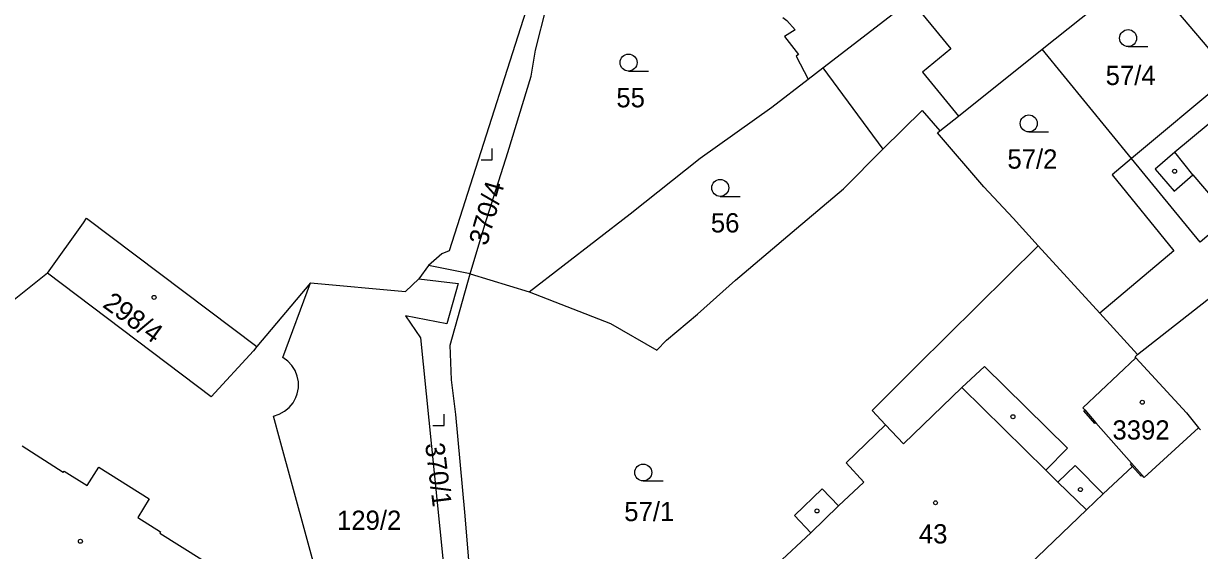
# Model space of a CAD drawing. Extents: x -679220 to -673243, y -1075091 to -1066557.
# Drawn here: x -676665 to -676560.9, y -1071449.2 to -1071402.6 of the extents above; entities that cross this region are included whole.
import ezdxf

# ---------------------------------------------------------------- set-up
doc = ezdxf.new("R2010")
doc.units = 0
for name, color, linetype in [('Hranice parcel', 7, 'Continuous'), ('Parcelní čísla', 7, 'Continuous'), ('Vnitřní kresba', 7, 'Continuous'), ('Značky budov', 7, 'Continuous'), ('Značky kultur', 7, 'Continuous')]:
    doc.layers.add(name, color=color, linetype=linetype)

msp = doc.modelspace()

# ---------------------------------------------------------------- linework, layer by layer
at = {"layer": 'Hranice parcel'}
for p, q in [((-676574.86, -1071404.84), (-676566.05, -1071397.82)), ((-676566.05, -1071397.82), (-676558.15, -1071407.15)), ((-676566.95, -1071414.5), (-676574.86, -1071404.84)), ((-676595.55, -1071407.49), (-676594.27, -1071406.5)), ((-676594.27, -1071406.5), (-676588.94, -1071413.68)), ((-676558.15, -1071407.15), (-676566.95, -1071414.5)), ((-676569.76, -1071428.19), (-676575.21, -1071422.22)), ((-676629.15, -1071423.95), (-676629.99, -1071425.14)), ((-676625.45, -1071424.7), (-676629.15, -1071423.95)), ((-676662.84, -1071424.65), (-676670.63, -1071430.85)), ((-676625.45, -1071424.7), (-676620.24, -1071426.29)), ((-676639.58, -1071425.49), (-676644.31, -1071431.12)), ((-676642.01, -1071432.1), (-676639.58, -1071425.49)), ((-676566.43, -1071431.83), (-676569.76, -1071428.19)), ((-676560.86, -1071438.5), (-676561.02, -1071438.3))]:
    msp.add_line(p, q, dxfattribs=at)
for points in [[(-676617.88, -1071388.31), (-676618.61, -1071388.69), (-676619.11, -1071389.11), (-676619.75, -1071389.94), (-676620.01, -1071390.56), (-676620.07, -1071392.77), (-676619.59, -1071394.13), (-676619.18, -1071394.93), (-676618.66, -1071395.65), (-676627.3, -1071422.68), (-676627.95, -1071422.94), (-676629.15, -1071423.95)], [(-676625.45, -1071424.7), (-676624.15, -1071420.38), (-676622.13, -1071413.98), (-676620.04, -1071407.23), (-676619.66, -1071404.92), (-676618.7, -1071401.1), (-676617.84, -1071396.43), (-676618.04, -1071394.99), (-676619.3, -1071392.29), (-676618.86, -1071390.8), (-676617.78, -1071390.15), (-676616.76, -1071389.74), (-676615.7, -1071390.33), (-676615.42, -1071389.7)], [(-676594.27, -1071406.5), (-676586.46, -1071400.51), (-676585.72, -1071399.94), (-676583.23, -1071398.03), (-676572.66, -1071389.87)], [(-676597.79, -1071402.04), (-676597.44, -1071402.3), (-676596.7, -1071403.12), (-676597.65, -1071403.73), (-676596.42, -1071405.3), (-676596.62, -1071405.46), (-676595.55, -1071407.49)], [(-676583.91, -1071412.06), (-676582.27, -1071410.75), (-676574.86, -1071404.84)], [(-676620.24, -1071426.29), (-676611.29, -1071419.39), (-676605.1, -1071414.47), (-676598.76, -1071409.97), (-676595.55, -1071407.49)], [(-676588.94, -1071413.68), (-676587.18, -1071411.93), (-676585.48, -1071410.26), (-676583.91, -1071412.06)], [(-676575.21, -1071422.22), (-676577.43, -1071419.78), (-676580.01, -1071417), (-676584.11, -1071412.24), (-676583.91, -1071412.06)], [(-676620.24, -1071426.29), (-676613.03, -1071429.08), (-676608.93, -1071431.46), (-676608.08, -1071430.55), (-676605.33, -1071428.25), (-676601.97, -1071425.26), (-676596.59, -1071420.68), (-676592.44, -1071417.18), (-676588.94, -1071413.68)], [(-676566.95, -1071414.5), (-676568.67, -1071415.94), (-676563.2, -1071422.66), (-676569.76, -1071428.19)], [(-676550.13, -1071416.68), (-676556.21, -1071421.85), (-676556.38, -1071422.01), (-676558.31, -1071419.73), (-676560.88, -1071421.91), (-676566.95, -1071414.5)], [(-676662.84, -1071424.65), (-676659.66, -1071420.19), (-676659.39, -1071419.78), (-676644.31, -1071431.12)], [(-676575.21, -1071422.22), (-676585.95, -1071432.82), (-676589.88, -1071436.78), (-676588.71, -1071438.04), (-676592.2, -1071441.42), (-676590.62, -1071443.1), (-676592.88, -1071445.22), (-676594.32, -1071443.69), (-676596.77, -1071446.05), (-676595.33, -1071447.58), (-676598.3, -1071450.36), (-676587.79, -1071461.53)], [(-676566.43, -1071431.83), (-676555.25, -1071423.07), (-676554.99, -1071422.87), (-676554.89, -1071423.01), (-676554.71, -1071422.88), (-676554.42, -1071423.27), (-676549.68, -1071428.95)], [(-676644.31, -1071431.12), (-676644.61, -1071431.52), (-676648.35, -1071435.57), (-676662.84, -1071424.65)], [(-676639.58, -1071425.49), (-676631.17, -1071426.26), (-676629.99, -1071425.14)], [(-676629.99, -1071425.14), (-676626.5, -1071425.54), (-676627.51, -1071429.11), (-676631.18, -1071428.42), (-676629.85, -1071430.36), (-676627.63, -1071452.18), (-676627.06, -1071457.4), (-676627.95, -1071458.12), (-676628.5, -1071459.17), (-676628.73, -1071459.98)], [(-676624.32, -1071460.51), (-676624.77, -1071456.53), (-676625.37, -1071452.45), (-676625.93, -1071445.76), (-676626.71, -1071437.13), (-676627.11, -1071434.06), (-676627.22, -1071431), (-676625.45, -1071424.7)], [(-676642.84, -1071437.27), (-676642.34, -1071437.11), (-676641.87, -1071436.85), (-676641.46, -1071436.52), (-676641.12, -1071436.11), (-676640.86, -1071435.64), (-676640.74, -1071435.31), (-676640.64, -1071434.79), (-676640.64, -1071434.26), (-676640.74, -1071433.74), (-676640.94, -1071433.25), (-676641.22, -1071432.8), (-676641.58, -1071432.41), (-676642.01, -1071432.1)], [(-676566.87, -1071441.72), (-676567.04, -1071441.52), (-676566.95, -1071441.44), (-676570.1, -1071437.86), (-676570.19, -1071437.94), (-676571.18, -1071436.81), (-676571.09, -1071436.73), (-676571.25, -1071436.55), (-676566.56, -1071432.12)], [(-676566.56, -1071432.12), (-676566.64, -1071432.03), (-676566.43, -1071431.83)], [(-676566.56, -1071432.12), (-676562.09, -1071436.98), (-676561.02, -1071438.3)], [(-676636.38, -1071460.95), (-676636.42, -1071460.8), (-676642.28, -1071439.33), (-676642.84, -1071437.27)], [(-676561.02, -1071438.3), (-676565.83, -1071442.71), (-676566, -1071442.51), (-676566.1, -1071442.59), (-676566.87, -1071441.72)], [(-676557.42, -1071466.86), (-676557.95, -1071466.4), (-676558.07, -1071466.32), (-676558.3, -1071466.23), (-676558.56, -1071466.19), (-676558.82, -1071466.22), (-676559.09, -1071466.31), (-676559.32, -1071466.47), (-676559.94, -1071467.01), (-676560.51, -1071466.49), (-676560.28, -1071466.24), (-676576.7, -1071451.11), (-676570.92, -1071445.57), (-676569.45, -1071444.14), (-676566.87, -1071441.72)]]:
    msp.add_lwpolyline(points, dxfattribs=at)
at = {"layer": 'Vnitřní kresba'}
for p, q in [((-676586.46, -1071400.51), (-676582.93, -1071404.81)), ((-676582.93, -1071404.81), (-676585.44, -1071406.87)), ((-676585.44, -1071406.87), (-676582.27, -1071410.75)), ((-676556.84, -1071408.71), (-676563.12, -1071413.94)), ((-676563.12, -1071413.94), (-676564.85, -1071415.45)), ((-676561.53, -1071415.94), (-676563.12, -1071413.94)), ((-676564.85, -1071415.45), (-676563.18, -1071417.38)), ((-676563.18, -1071417.38), (-676561.53, -1071415.94)), ((-676561.53, -1071415.94), (-676558.31, -1071419.73)), ((-676581.95, -1071434.76), (-676579.96, -1071432.88)), ((-676579.96, -1071432.88), (-676572.62, -1071440.12)), ((-676587.13, -1071439.72), (-676581.95, -1071434.76)), ((-676581.95, -1071434.76), (-676574.53, -1071442.05)), ((-676571.09, -1071436.73), (-676570.1, -1071437.86)), ((-676588.71, -1071438.04), (-676587.13, -1071439.72)), ((-676661.44, -1071442.27), (-676665.07, -1071439.94)), ((-676574.53, -1071442.05), (-676572.62, -1071440.12)), ((-676659.34, -1071443.41), (-676658.31, -1071441.78)), ((-676658.31, -1071441.78), (-676653.84, -1071444.6)), ((-676573.46, -1071443.1), (-676571.95, -1071441.65)), ((-676569.45, -1071444.14), (-676571.95, -1071441.65)), ((-676566.95, -1071441.44), (-676566, -1071442.51)), ((-676661.44, -1071442.27), (-676661.35, -1071442.14)), ((-676661.35, -1071442.14), (-676659.34, -1071443.41)), ((-676574.53, -1071442.05), (-676573.46, -1071443.1)), ((-676573.46, -1071443.1), (-676570.92, -1071445.57)), ((-676653.84, -1071444.6), (-676654.84, -1071446.24)), ((-676595.33, -1071447.58), (-676592.88, -1071445.22)), ((-676654.84, -1071446.24), (-676652.83, -1071447.51)), ((-676652.83, -1071447.51), (-676652.91, -1071447.63)), ((-676652.91, -1071447.63), (-676649.19, -1071449.94))]:
    msp.add_line(p, q, dxfattribs=at)
at = {"layer": 'Značky budov'}
for centre in [(-676563.14, -1071415.63), (-676653.41, -1071426.78), (-676566, -1071436.05), (-676577.44, -1071437.33), (-676571.47, -1071443.77), (-676584.29, -1071444.94), (-676594.77, -1071445.66), (-676659.93, -1071448.34)]:
    msp.add_circle(centre, 0.175, dxfattribs=at)
at = {"layer": 'Značky kultur'}
for p, q in [((-676567.25, -1071404.61), (-676565.5, -1071404.61)), ((-676611.44, -1071406.78), (-676609.69, -1071406.78)), ((-676576.04, -1071412.15), (-676574.29, -1071412.15)), ((-676623.49, -1071414.63), (-676623.49, -1071413.63)), ((-676624.49, -1071414.63), (-676623.49, -1071414.63)), ((-676603.33, -1071417.85), (-676601.58, -1071417.85)), ((-676627.76, -1071438.11), (-676627.76, -1071437.11)), ((-676628.76, -1071438.11), (-676627.76, -1071438.11)), ((-676610.14, -1071443.01), (-676608.39, -1071443.01))]:
    msp.add_line(p, q, dxfattribs=at)
for centre in [(-676567.25, -1071403.86), (-676611.44, -1071406.03), (-676576.04, -1071411.4), (-676603.33, -1071417.1), (-676610.14, -1071442.26)]:
    msp.add_circle(centre, 0.75, dxfattribs=at)

# ---------------------------------------------------------------- texts
at = {"layer": 'Parcelní čísla'}
for s, p in [('57/4', (-676569.24, -1071408.01)), ('55', (-676612.52, -1071409.98)), ('57/2', (-676577.93, -1071415.4)), ('56', (-676604.16, -1071421.04)), ('3392', (-676568.64, -1071439.35)), ('57/1', (-676611.82, -1071446.56)), ('129/2', (-676637.23, -1071447.33)), ('43', (-676585.76, -1071448.53))]:
    msp.add_text(s, height=1.7, dxfattribs=at).set_placement(p)
for s, rotation, p in [('370/4', 74, (-676623.97, -1071422.29)), ('298/4', 324, (-676658.05, -1071427.57)), ('370/1', 277, (-676629.44, -1071439.73))]:
    msp.add_text(s, height=1.7, rotation=rotation, dxfattribs=at).set_placement(p)

doc.saveas('drawing.dxf')
